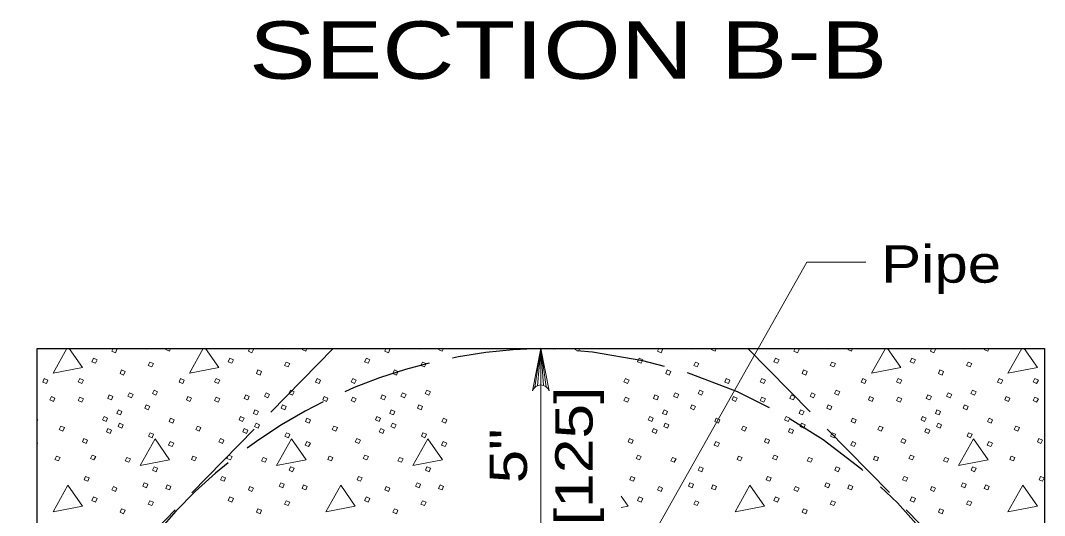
# Model space of a CAD drawing. Extents: x 1036.7 to 1070.7, y 883.9 to 905.9.
# Drawn here: x 1045.658 to 1049.935, y 891.176 to 893.244 of the extents above; entities that cross this region are included whole.
import ezdxf
from ezdxf.enums import TextEntityAlignment as Align

# ---------------------------------------------------------------- set-up
doc = ezdxf.new("R2010")
doc.units = 0
doc.header["$LTSCALE"] = 0.062
doc.linetypes.add('LONG_DASHED', pattern=[7.5, 6, -1.5])
doc.layers.add('1', color=7, linetype='Continuous', lineweight=13)

msp = doc.modelspace()

# ---------------------------------------------------------------- linework, layer by layer
at = {"layer": '1', "linetype": 'LONG_DASHED', "lineweight": 25}
for p, q in [((1046.96408, 891.87417), (1045.72733, 890.60908)), ((1048.6965, 891.87417), (1049.935, 890.61017))]:
    msp.add_line(p, q, dxfattribs=at)
at = {"layer": '1'}
for p, q in [((1047.80642, 891.71208), (1047.83117, 891.87417)), ((1047.81683, 891.71817), (1047.83117, 891.87417)), ((1047.83117, 891.87417), (1047.83117, 891.574)), ((1047.83117, 891.721), (1047.83117, 891.87417)), ((1047.8425, 891.71933), (1047.83117, 891.87417)), ((1047.85358, 891.71392), (1047.83117, 891.87417)), ((1047.83117, 890.974), (1047.83117, 891.574))]:
    msp.add_line(p, q, dxfattribs=at)
for points in [[(1048.20325, 890.92225), (1048.94275, 892.23433), (1049.18883, 892.23433)], [(1045.85192, 891.87417), (1045.79408, 891.77075), (1045.917, 891.79475), (1045.86133, 891.87417)], [(1046.05125, 891.87417), (1046.06092, 891.86967), (1046.05492, 891.85567), (1046.04, 891.86267), (1046.04492, 891.87417)], [(1046.18533, 891.87417), (1046.18392, 891.87067), (1046.17642, 891.87417)], [(1046.28475, 891.87417), (1046.27983, 891.86267), (1046.26483, 891.86867), (1046.267, 891.87417)], [(1046.42158, 891.87417), (1046.36383, 891.77075), (1046.48675, 891.79475), (1046.431, 891.87417)], [(1046.621, 891.87417), (1046.63067, 891.86967), (1046.62467, 891.85567), (1046.60967, 891.86267), (1046.61458, 891.87417)], [(1046.75508, 891.87417), (1046.75367, 891.87067), (1046.74617, 891.87417)], [(1046.8545, 891.87417), (1046.84958, 891.86267), (1046.83458, 891.86867), (1046.83675, 891.87417)], [(1047.19075, 891.87417), (1047.20042, 891.86967), (1047.19442, 891.85567), (1047.17942, 891.86267), (1047.18433, 891.87417)], [(1047.32475, 891.87417), (1047.32333, 891.87067), (1047.31583, 891.87417)], [(1047.42425, 891.87417), (1047.41933, 891.86267), (1047.40433, 891.86867), (1047.4065, 891.87417)], [(1047.79583, 891.69717), (1047.83117, 891.87417), (1047.86658, 891.69717)], [(1047.8945, 891.87417), (1047.89308, 891.87067), (1047.88558, 891.87417)], [(1047.994, 891.87417), (1047.98908, 891.86267), (1047.97408, 891.86867), (1047.97625, 891.87417)], [(1048.33025, 891.87417), (1048.33992, 891.86967), (1048.33392, 891.85567), (1048.31892, 891.86267), (1048.32383, 891.87417)], [(1048.46425, 891.87417), (1048.46283, 891.87067), (1048.45533, 891.87417)], [(1048.56367, 891.87417), (1048.55875, 891.86267), (1048.54375, 891.86867), (1048.54592, 891.87417)], [(1048.89992, 891.87417), (1048.90958, 891.86967), (1048.90358, 891.85567), (1048.88858, 891.86267), (1048.8935, 891.87417)], [(1049.034, 891.87417), (1049.03258, 891.87067), (1049.02508, 891.87417)], [(1049.13342, 891.87417), (1049.1285, 891.86267), (1049.1135, 891.86867), (1049.11567, 891.87417)], [(1049.27025, 891.87417), (1049.2125, 891.77075), (1049.33542, 891.79475), (1049.27967, 891.87417)], [(1049.46967, 891.87417), (1049.47933, 891.86967), (1049.47333, 891.85567), (1049.45833, 891.86267), (1049.46325, 891.87417)], [(1049.60367, 891.87417), (1049.60225, 891.87067), (1049.59475, 891.87417)], [(1049.70317, 891.87417), (1049.69825, 891.86267), (1049.68325, 891.86867), (1049.68542, 891.87417)], [(1049.84, 891.87417), (1049.78217, 891.77075), (1049.90517, 891.79475), (1049.84942, 891.87417)], [(1045.72733, 891.57708), (1045.73008, 891.57583), (1045.72733, 891.56942)], [(1045.72733, 891.47875), (1045.72908, 891.47792), (1045.72733, 891.47442)], [(1048.16733, 891.2095), (1048.19592, 891.21508), (1048.16733, 891.25592)]]:
    msp.add_lwpolyline(points, dxfattribs=at)
at = {"layer": '1', "lineweight": 25}
for points in [[(1045.72733, 891.87417), (1049.935, 891.87417), (1049.935, 887.57667), (1047.83117, 887.57667)], [(1047.83117, 887.57667), (1045.72733, 887.57667), (1045.72733, 891.87417)]]:
    msp.add_lwpolyline(points, dxfattribs=at)
at = {"layer": '1'}
for points in [[(1045.963, 891.83275), (1045.978, 891.82575), (1045.971, 891.81175), (1045.956, 891.81775)], [(1046.19792, 891.81675), (1046.21292, 891.81075), (1046.20592, 891.79675), (1046.19092, 891.80275)], [(1046.53275, 891.83275), (1046.54775, 891.82575), (1046.54075, 891.81175), (1046.52575, 891.81775)], [(1046.76758, 891.81675), (1046.78258, 891.81075), (1046.77558, 891.79675), (1046.76058, 891.80275)], [(1047.1025, 891.83275), (1047.11742, 891.82575), (1047.11042, 891.81175), (1047.0955, 891.81775)], [(1047.33733, 891.81675), (1047.35233, 891.81075), (1047.34533, 891.79675), (1047.33033, 891.80275)], [(1048.24192, 891.83275), (1048.25692, 891.82575), (1048.24992, 891.81175), (1048.23492, 891.81775)], [(1048.47683, 891.81675), (1048.49183, 891.81075), (1048.48483, 891.79675), (1048.46983, 891.80275)], [(1048.81167, 891.83275), (1048.82667, 891.82575), (1048.81967, 891.81175), (1048.80467, 891.81775)], [(1049.04658, 891.81675), (1049.0615, 891.81075), (1049.05458, 891.79675), (1049.03958, 891.80275)], [(1049.38142, 891.83275), (1049.39642, 891.82575), (1049.38942, 891.81175), (1049.37442, 891.81775)], [(1049.61625, 891.81675), (1049.63125, 891.81075), (1049.62425, 891.79675), (1049.60925, 891.80275)], [(1046.07992, 891.78375), (1046.09492, 891.77775), (1046.08892, 891.76275), (1046.07392, 891.76975)], [(1046.64967, 891.78375), (1046.66467, 891.77775), (1046.65867, 891.76275), (1046.64367, 891.76975)], [(1047.21942, 891.78375), (1047.23442, 891.77775), (1047.22842, 891.76275), (1047.21342, 891.76975)], [(1048.35883, 891.78375), (1048.37383, 891.77775), (1048.36783, 891.76275), (1048.35292, 891.76975)], [(1048.92858, 891.78375), (1048.94358, 891.77775), (1048.93758, 891.76275), (1048.92258, 891.76975)], [(1049.49833, 891.78375), (1049.51333, 891.77775), (1049.50733, 891.76275), (1049.49233, 891.76975)], [(1045.75708, 891.74775), (1045.77208, 891.74075), (1045.76608, 891.72675), (1045.75108, 891.73275)], [(1045.906, 891.74775), (1045.921, 891.74175), (1045.914, 891.72775), (1045.899, 891.73375)], [(1046.32683, 891.74775), (1046.34183, 891.74075), (1046.33583, 891.72675), (1046.32083, 891.73275)], [(1046.47575, 891.74775), (1046.49075, 891.74175), (1046.48375, 891.72775), (1046.46875, 891.73375)], [(1046.89658, 891.74775), (1046.91158, 891.74075), (1046.90558, 891.72675), (1046.89058, 891.73275)], [(1047.0455, 891.74775), (1047.0605, 891.74175), (1047.0535, 891.72775), (1047.0385, 891.73375)], [(1048.18492, 891.74775), (1048.19992, 891.74175), (1048.19292, 891.72775), (1048.17792, 891.73375)], [(1048.60575, 891.74775), (1048.62075, 891.74075), (1048.61475, 891.72675), (1048.59975, 891.73275)], [(1048.75467, 891.74775), (1048.76967, 891.74175), (1048.76267, 891.72775), (1048.74767, 891.73375)], [(1049.1755, 891.74775), (1049.1905, 891.74075), (1049.1845, 891.72675), (1049.1695, 891.73275)], [(1049.32442, 891.74775), (1049.33942, 891.74175), (1049.33242, 891.72775), (1049.31742, 891.73375)], [(1049.74525, 891.74775), (1049.76025, 891.74075), (1049.75425, 891.72675), (1049.73925, 891.73275)], [(1049.89417, 891.74775), (1049.90917, 891.74175), (1049.90217, 891.72775), (1049.88717, 891.73375)], [(1046.029, 891.67983), (1046.044, 891.67283), (1046.038, 891.65883), (1046.023, 891.66483)], [(1046.11392, 891.68783), (1046.12892, 891.68183), (1046.12192, 891.66683), (1046.10692, 891.67383)], [(1046.21592, 891.69975), (1046.23083, 891.69283), (1046.22392, 891.67883), (1046.20892, 891.68583)], [(1046.59867, 891.67983), (1046.61367, 891.67283), (1046.60767, 891.65883), (1046.59267, 891.66483)], [(1046.68367, 891.68783), (1046.69867, 891.68183), (1046.69167, 891.66683), (1046.67667, 891.67383)], [(1046.78558, 891.69975), (1046.80058, 891.69283), (1046.79358, 891.67883), (1046.77858, 891.68583)], [(1047.16842, 891.67983), (1047.18342, 891.67283), (1047.17742, 891.65883), (1047.16242, 891.66483)], [(1047.25342, 891.68783), (1047.26842, 891.68183), (1047.26142, 891.66683), (1047.24642, 891.67383)], [(1047.35533, 891.69975), (1047.37033, 891.69283), (1047.36333, 891.67883), (1047.34833, 891.68583)], [(1048.30792, 891.67983), (1048.32292, 891.67283), (1048.31692, 891.65883), (1048.30192, 891.66483)], [(1048.39283, 891.68783), (1048.40783, 891.68183), (1048.40083, 891.66683), (1048.38583, 891.67383)], [(1048.49483, 891.69975), (1048.50983, 891.69283), (1048.50283, 891.67883), (1048.48783, 891.68583)], [(1048.87767, 891.67983), (1048.89258, 891.67283), (1048.88658, 891.65883), (1048.87167, 891.66483)], [(1048.96258, 891.68783), (1048.97758, 891.68183), (1048.97058, 891.66683), (1048.95558, 891.67383)], [(1049.0645, 891.69975), (1049.0795, 891.69283), (1049.0725, 891.67883), (1049.05758, 891.68583)], [(1049.44733, 891.67983), (1049.46233, 891.67283), (1049.45633, 891.65883), (1049.44133, 891.66483)], [(1049.53233, 891.68783), (1049.54733, 891.68183), (1049.54033, 891.66683), (1049.52533, 891.67383)], [(1049.63425, 891.69975), (1049.64925, 891.69283), (1049.64225, 891.67883), (1049.62725, 891.68583)], [(1045.78708, 891.67283), (1045.80208, 891.66583), (1045.79608, 891.65183), (1045.78108, 891.65883)], [(1045.906, 891.66983), (1045.921, 891.66383), (1045.914, 891.64883), (1045.899, 891.65583)], [(1046.18292, 891.63783), (1046.19792, 891.63083), (1046.19192, 891.61683), (1046.17692, 891.62383)], [(1046.35683, 891.67283), (1046.37183, 891.66583), (1046.36583, 891.65183), (1046.35083, 891.65883)], [(1046.47575, 891.66983), (1046.49075, 891.66383), (1046.48375, 891.64883), (1046.46875, 891.65583)], [(1046.75267, 891.63783), (1046.76758, 891.63083), (1046.76158, 891.61683), (1046.74667, 891.62383)], [(1046.92658, 891.67283), (1046.9415, 891.66583), (1046.93558, 891.65183), (1046.92058, 891.65883)], [(1047.0455, 891.66983), (1047.0605, 891.66383), (1047.0535, 891.64883), (1047.0385, 891.65583)], [(1047.32233, 891.63783), (1047.33733, 891.63083), (1047.33133, 891.61683), (1047.31633, 891.62383)], [(1048.18492, 891.66983), (1048.19992, 891.66383), (1048.19292, 891.64883), (1048.17792, 891.65583)], [(1048.46183, 891.63783), (1048.47683, 891.63083), (1048.47083, 891.61683), (1048.45583, 891.62383)], [(1048.63575, 891.67283), (1048.65075, 891.66583), (1048.64475, 891.65183), (1048.62975, 891.65883)], [(1048.75467, 891.66983), (1048.76967, 891.66383), (1048.76267, 891.64883), (1048.74767, 891.65583)], [(1049.03158, 891.63783), (1049.04658, 891.63083), (1049.04058, 891.61683), (1049.02558, 891.62383)], [(1049.2055, 891.67283), (1049.2205, 891.66583), (1049.2145, 891.65183), (1049.1995, 891.65883)], [(1049.32442, 891.66983), (1049.33942, 891.66383), (1049.33242, 891.64883), (1049.31742, 891.65583)], [(1049.60125, 891.63783), (1049.61625, 891.63083), (1049.61025, 891.61683), (1049.59525, 891.62383)], [(1049.77517, 891.67283), (1049.79017, 891.66583), (1049.78417, 891.65183), (1049.76917, 891.65883)], [(1049.89417, 891.66983), (1049.90917, 891.66383), (1049.90217, 891.64883), (1049.88717, 891.65583)], [(1046.06692, 891.61683), (1046.08192, 891.60983), (1046.07592, 891.59583), (1046.06092, 891.60183)], [(1046.63667, 891.61683), (1046.65167, 891.60983), (1046.64567, 891.59583), (1046.63067, 891.60183)], [(1047.20642, 891.61683), (1047.22142, 891.60983), (1047.21542, 891.59583), (1047.20042, 891.60183)], [(1048.34592, 891.61683), (1048.36083, 891.60983), (1048.35483, 891.59583), (1048.33992, 891.60183)], [(1048.91558, 891.61683), (1048.93058, 891.60983), (1048.92458, 891.59583), (1048.90958, 891.60183)], [(1049.48533, 891.61683), (1049.50033, 891.60983), (1049.49433, 891.59583), (1049.47933, 891.60183)], [(1045.82708, 891.54892), (1045.84208, 891.54292), (1045.83508, 891.52792), (1045.82008, 891.53492)], [(1046.007, 891.58883), (1046.022, 891.58283), (1046.016, 891.56883), (1046.001, 891.57483)], [(1046.07192, 891.56183), (1046.08692, 891.55483), (1046.08092, 891.54092), (1046.06592, 891.54792)], [(1046.28483, 891.58283), (1046.29983, 891.57583), (1046.29383, 891.56183), (1046.27883, 891.56783)], [(1046.39683, 891.54892), (1046.41175, 891.54292), (1046.40475, 891.52792), (1046.38983, 891.53492)], [(1046.57675, 891.58883), (1046.59167, 891.58283), (1046.58567, 891.56883), (1046.57075, 891.57483)], [(1046.64167, 891.56183), (1046.65667, 891.55483), (1046.65067, 891.54092), (1046.63567, 891.54792)], [(1046.85458, 891.58283), (1046.86958, 891.57583), (1046.86358, 891.56183), (1046.84858, 891.56783)], [(1046.9665, 891.54892), (1046.9815, 891.54292), (1046.9745, 891.52792), (1046.9595, 891.53492)], [(1047.14642, 891.58883), (1047.16142, 891.58283), (1047.15542, 891.56883), (1047.14042, 891.57483)], [(1047.21142, 891.56183), (1047.22642, 891.55483), (1047.22042, 891.54092), (1047.20542, 891.54792)], [(1047.42433, 891.58283), (1047.43933, 891.57583), (1047.43333, 891.56183), (1047.41833, 891.56783)], [(1048.28592, 891.58883), (1048.30092, 891.58283), (1048.29492, 891.56883), (1048.27992, 891.57483)], [(1048.35083, 891.56183), (1048.36583, 891.55483), (1048.35983, 891.54092), (1048.34492, 891.54792)], [(1048.56375, 891.58283), (1048.57875, 891.57583), (1048.57275, 891.56183), (1048.55775, 891.56783)], [(1048.67575, 891.54892), (1048.69075, 891.54292), (1048.68375, 891.52792), (1048.66875, 891.53492)], [(1048.85567, 891.58883), (1048.87067, 891.58283), (1048.86467, 891.56883), (1048.84967, 891.57483)], [(1048.92058, 891.56183), (1048.93558, 891.55483), (1048.92958, 891.54092), (1048.91458, 891.54792)], [(1049.1335, 891.58283), (1049.1485, 891.57583), (1049.1425, 891.56183), (1049.1275, 891.56783)], [(1049.24542, 891.54892), (1049.26042, 891.54292), (1049.25342, 891.52792), (1049.23842, 891.53492)], [(1049.42533, 891.58883), (1049.44033, 891.58283), (1049.43433, 891.56883), (1049.41933, 891.57483)], [(1049.49033, 891.56183), (1049.50533, 891.55483), (1049.49933, 891.54092), (1049.48433, 891.54792)], [(1049.70325, 891.58283), (1049.71825, 891.57583), (1049.71225, 891.56183), (1049.69725, 891.56783)], [(1049.81517, 891.54892), (1049.83017, 891.54292), (1049.82317, 891.52792), (1049.80817, 891.53492)], [(1046.023, 891.53892), (1046.038, 891.53192), (1046.032, 891.51792), (1046.017, 891.52492)], [(1046.19892, 891.52092), (1046.21392, 891.51492), (1046.20792, 891.49992), (1046.19292, 891.50692)], [(1046.59267, 891.53892), (1046.60767, 891.53192), (1046.60167, 891.51792), (1046.58667, 891.52492)], [(1046.76858, 891.52092), (1046.78358, 891.51492), (1046.77758, 891.49992), (1046.76258, 891.50692)], [(1047.16242, 891.53892), (1047.17742, 891.53192), (1047.17142, 891.51792), (1047.15642, 891.52492)], [(1047.33833, 891.52092), (1047.35333, 891.51492), (1047.34733, 891.49992), (1047.33233, 891.50692)], [(1048.30192, 891.53892), (1048.31692, 891.53192), (1048.31092, 891.51792), (1048.29592, 891.52492)], [(1048.87167, 891.53892), (1048.88658, 891.53192), (1048.88067, 891.51792), (1048.86567, 891.52492)], [(1049.04758, 891.52092), (1049.0625, 891.51492), (1049.0565, 891.49992), (1049.04158, 891.50692)], [(1049.44133, 891.53892), (1049.45633, 891.53192), (1049.45033, 891.51792), (1049.43533, 891.52492)], [(1049.61725, 891.52092), (1049.63225, 891.51492), (1049.62625, 891.49992), (1049.61125, 891.50692)], [(1045.923, 891.49692), (1045.938, 891.49092), (1045.932, 891.47692), (1045.917, 891.48292)], [(1046.21992, 891.49592), (1046.15792, 891.385), (1046.28083, 891.40892)], [(1046.28383, 891.48492), (1046.29883, 891.47792), (1046.29183, 891.46392), (1046.27683, 891.46992)], [(1046.49275, 891.49692), (1046.50775, 891.49092), (1046.50175, 891.47692), (1046.48675, 891.48292)], [(1046.78958, 891.49592), (1046.72767, 891.385), (1046.85058, 891.40892)], [(1046.85358, 891.48492), (1046.86858, 891.47792), (1046.86158, 891.46392), (1046.84658, 891.46992)], [(1047.0625, 891.49692), (1047.0775, 891.49092), (1047.0715, 891.47692), (1047.0565, 891.48292)], [(1047.35933, 891.49592), (1047.29733, 891.385), (1047.42033, 891.40892)], [(1047.42333, 891.48492), (1047.43833, 891.47792), (1047.43133, 891.46392), (1047.41633, 891.46992)], [(1048.20192, 891.49692), (1048.21692, 891.49092), (1048.21092, 891.47692), (1048.19592, 891.48292)], [(1048.56275, 891.48492), (1048.57775, 891.47792), (1048.57075, 891.46392), (1048.55575, 891.46992)], [(1048.77167, 891.49692), (1048.78667, 891.49092), (1048.78067, 891.47692), (1048.76567, 891.48292)], [(1049.1325, 891.48492), (1049.1475, 891.47792), (1049.1405, 891.46392), (1049.1255, 891.46992)], [(1049.34142, 891.49692), (1049.35642, 891.49092), (1049.35042, 891.47692), (1049.33542, 891.48292)], [(1049.63825, 891.49592), (1049.57633, 891.385), (1049.69925, 891.40892)], [(1049.70225, 891.48492), (1049.71725, 891.47792), (1049.71025, 891.46392), (1049.69525, 891.46992)], [(1049.91117, 891.49692), (1049.92617, 891.49092), (1049.92017, 891.47692), (1049.90517, 891.48292)], [(1045.80808, 891.42392), (1045.82308, 891.41792), (1045.81708, 891.404), (1045.80208, 891.40992)], [(1045.957, 891.42792), (1045.972, 891.42192), (1045.965, 891.40792), (1045.95, 891.41392)], [(1046.37783, 891.42392), (1046.39283, 891.41792), (1046.38683, 891.404), (1046.37183, 891.40992)], [(1046.52675, 891.42792), (1046.54175, 891.42192), (1046.53475, 891.40792), (1046.51975, 891.41392)], [(1046.9475, 891.42392), (1046.9625, 891.41792), (1046.9565, 891.404), (1046.9415, 891.40992)], [(1047.0965, 891.42792), (1047.1115, 891.42192), (1047.1045, 891.40792), (1047.0895, 891.41392)], [(1048.23592, 891.42792), (1048.25092, 891.42192), (1048.24392, 891.40792), (1048.22892, 891.41392)], [(1048.65675, 891.42392), (1048.67175, 891.41792), (1048.66575, 891.404), (1048.65075, 891.40992)], [(1048.80567, 891.42792), (1048.82067, 891.42192), (1048.81367, 891.40792), (1048.79867, 891.41392)], [(1049.2265, 891.42392), (1049.24142, 891.41792), (1049.2355, 891.404), (1049.2205, 891.40992)], [(1049.37542, 891.42792), (1049.39042, 891.42192), (1049.38342, 891.40792), (1049.36842, 891.41392)], [(1049.79617, 891.42392), (1049.81117, 891.41792), (1049.80517, 891.404), (1049.79017, 891.40992)], [(1046.10192, 891.41792), (1046.11692, 891.41192), (1046.10992, 891.398), (1046.09492, 891.404)], [(1046.21592, 891.379), (1046.23083, 891.373), (1046.22492, 891.358), (1046.20992, 891.365)], [(1046.67167, 891.41792), (1046.68667, 891.41192), (1046.67967, 891.398), (1046.66467, 891.404)], [(1046.78558, 891.379), (1046.80058, 891.373), (1046.79458, 891.358), (1046.77958, 891.365)], [(1047.24142, 891.41792), (1047.25642, 891.41192), (1047.24942, 891.398), (1047.23442, 891.404)], [(1047.35533, 891.379), (1047.37033, 891.373), (1047.36433, 891.358), (1047.34933, 891.365)], [(1048.38083, 891.41792), (1048.39583, 891.41192), (1048.38883, 891.398), (1048.37383, 891.404)], [(1048.49483, 891.379), (1048.50983, 891.373), (1048.50383, 891.358), (1048.48883, 891.365)], [(1048.95058, 891.41792), (1048.96558, 891.41192), (1048.95858, 891.398), (1048.94358, 891.404)], [(1049.0645, 891.379), (1049.0795, 891.373), (1049.0735, 891.358), (1049.05858, 891.365)], [(1049.52033, 891.41792), (1049.53533, 891.41192), (1049.52833, 891.398), (1049.51333, 891.404)], [(1049.63425, 891.379), (1049.64925, 891.373), (1049.64325, 891.358), (1049.62825, 891.365)], [(1045.93, 891.339), (1045.945, 891.333), (1045.939, 891.319), (1045.924, 891.325)], [(1046.49975, 891.339), (1046.51475, 891.333), (1046.50875, 891.319), (1046.49375, 891.325)], [(1047.0695, 891.339), (1047.0845, 891.333), (1047.0785, 891.319), (1047.0635, 891.325)], [(1048.20892, 891.339), (1048.22392, 891.333), (1048.21792, 891.319), (1048.20292, 891.325)], [(1048.77867, 891.339), (1048.79367, 891.333), (1048.78767, 891.319), (1048.77267, 891.325)], [(1049.34842, 891.339), (1049.36342, 891.333), (1049.35742, 891.319), (1049.34242, 891.325)], [(1049.91817, 891.339), (1049.93317, 891.333), (1049.92717, 891.319), (1049.91217, 891.325)], [(1045.85608, 891.302), (1045.79408, 891.19108), (1045.917, 891.21508)], [(1046.046, 891.297), (1046.06092, 891.29), (1046.05492, 891.276), (1046.04, 891.283)], [(1046.17492, 891.312), (1046.18992, 891.306), (1046.18392, 891.291), (1046.16892, 891.298)], [(1046.27083, 891.304), (1046.28583, 891.297), (1046.27983, 891.283), (1046.26483, 891.289)], [(1046.61567, 891.297), (1046.63067, 891.29), (1046.62467, 891.276), (1046.60967, 891.283)], [(1046.74467, 891.312), (1046.75958, 891.306), (1046.75367, 891.291), (1046.73867, 891.298)], [(1046.84058, 891.304), (1046.85558, 891.297), (1046.84958, 891.283), (1046.83458, 891.289)], [(1046.9955, 891.302), (1046.93358, 891.19108), (1047.0565, 891.21508)], [(1047.18542, 891.297), (1047.20042, 891.29), (1047.19442, 891.276), (1047.17942, 891.283)], [(1047.31433, 891.312), (1047.32933, 891.306), (1047.32333, 891.291), (1047.30833, 891.298)], [(1047.41033, 891.304), (1047.42533, 891.297), (1047.41933, 891.283), (1047.40433, 891.289)], [(1048.32492, 891.297), (1048.33992, 891.29), (1048.33392, 891.276), (1048.31892, 891.283)], [(1048.45383, 891.312), (1048.46883, 891.306), (1048.46283, 891.291), (1048.44783, 891.298)], [(1048.54975, 891.304), (1048.56475, 891.297), (1048.55875, 891.283), (1048.54375, 891.289)], [(1048.70475, 891.302), (1048.64275, 891.19108), (1048.76567, 891.21508)], [(1048.89458, 891.297), (1048.90958, 891.29), (1048.90358, 891.276), (1048.88858, 891.283)], [(1049.02358, 891.312), (1049.03858, 891.306), (1049.03258, 891.291), (1049.01758, 891.298)], [(1049.1195, 891.304), (1049.1345, 891.297), (1049.1285, 891.283), (1049.1135, 891.289)], [(1049.46433, 891.297), (1049.47933, 891.29), (1049.47333, 891.276), (1049.45833, 891.283)], [(1049.59333, 891.312), (1049.60825, 891.306), (1049.60225, 891.291), (1049.58733, 891.298)], [(1049.68925, 891.304), (1049.70425, 891.297), (1049.69825, 891.283), (1049.68325, 891.289)], [(1049.84417, 891.302), (1049.78217, 891.19108), (1049.90517, 891.21508)], [(1045.963, 891.25308), (1045.978, 891.24608), (1045.971, 891.23208), (1045.956, 891.23808)], [(1046.53275, 891.25308), (1046.54775, 891.24608), (1046.54075, 891.23208), (1046.52575, 891.23808)], [(1047.1025, 891.25308), (1047.11742, 891.24608), (1047.11042, 891.23208), (1047.0955, 891.23808)], [(1048.24192, 891.25308), (1048.25692, 891.24608), (1048.24992, 891.23208), (1048.23492, 891.23808)], [(1048.81167, 891.25308), (1048.82667, 891.24608), (1048.81967, 891.23208), (1048.80467, 891.23808)], [(1049.38142, 891.25308), (1049.39642, 891.24608), (1049.38942, 891.23208), (1049.37442, 891.23808)], [(1046.19792, 891.23708), (1046.21292, 891.23108), (1046.20592, 891.21708), (1046.19092, 891.22308)], [(1046.76758, 891.23708), (1046.78258, 891.23108), (1046.77558, 891.21708), (1046.76058, 891.22308)], [(1047.33733, 891.23708), (1047.35233, 891.23108), (1047.34533, 891.21708), (1047.33033, 891.22308)], [(1048.47683, 891.23708), (1048.49183, 891.23108), (1048.48483, 891.21708), (1048.46983, 891.22308)], [(1049.04658, 891.23708), (1049.0615, 891.23108), (1049.05458, 891.21708), (1049.03958, 891.22308)], [(1049.61625, 891.23708), (1049.63125, 891.23108), (1049.62425, 891.21708), (1049.60925, 891.22308)], [(1046.07992, 891.20408), (1046.09492, 891.19808), (1046.08892, 891.18308), (1046.07392, 891.19008)], [(1046.64967, 891.20408), (1046.66467, 891.19808), (1046.65867, 891.18308), (1046.64367, 891.19008)], [(1047.21942, 891.20408), (1047.23442, 891.19808), (1047.22842, 891.18308), (1047.21342, 891.19008)], [(1048.92858, 891.20408), (1048.94358, 891.19808), (1048.93758, 891.18308), (1048.92258, 891.19008)], [(1049.49833, 891.20408), (1049.51333, 891.19808), (1049.50733, 891.18308), (1049.49233, 891.19008)]]:
    msp.add_lwpolyline(points, close=True, dxfattribs=at)
msp.add_arc((1047.83124, 891.6829), 0.0382, 22.08782, 157.91395, dxfattribs=at)
at = {"layer": '1', "linetype": 'LONG_DASHED', "lineweight": 25}
for centre, major_axis, start_param, end_param in [((1047.87683, 889.72543), (-2.14947, 0), 4.7336189, 6.4365345), ((1047.78549, 889.72543), (2.14947, 0), 4.7336585, 7.8327121)]:
    msp.add_ellipse(centre, major_axis=major_axis, ratio=0.999895, start_param=start_param, end_param=end_param, dxfattribs=at)

# ---------------------------------------------------------------- texts
at = {"layer": '1'}
for s, height, width, p in [('SECTION B-B', 0.24, 1.3, (1046.61242, 893.00067)), ('Pipe', 0.156, 1.2, (1049.25275, 892.1485))]:
    msp.add_text(s, height=height, dxfattribs=dict(at, width=width)).set_placement(p)
for s, width, p in [('[125]', 1.25, (1048.0475, 891.42467)), ('5"', 1.2, (1047.7735, 891.42471))]:
    msp.add_text(s, height=0.156, rotation=90, dxfattribs=dict(at, width=width)).set_placement(p, align=Align.CENTER)

doc.saveas('drawing.dxf')
